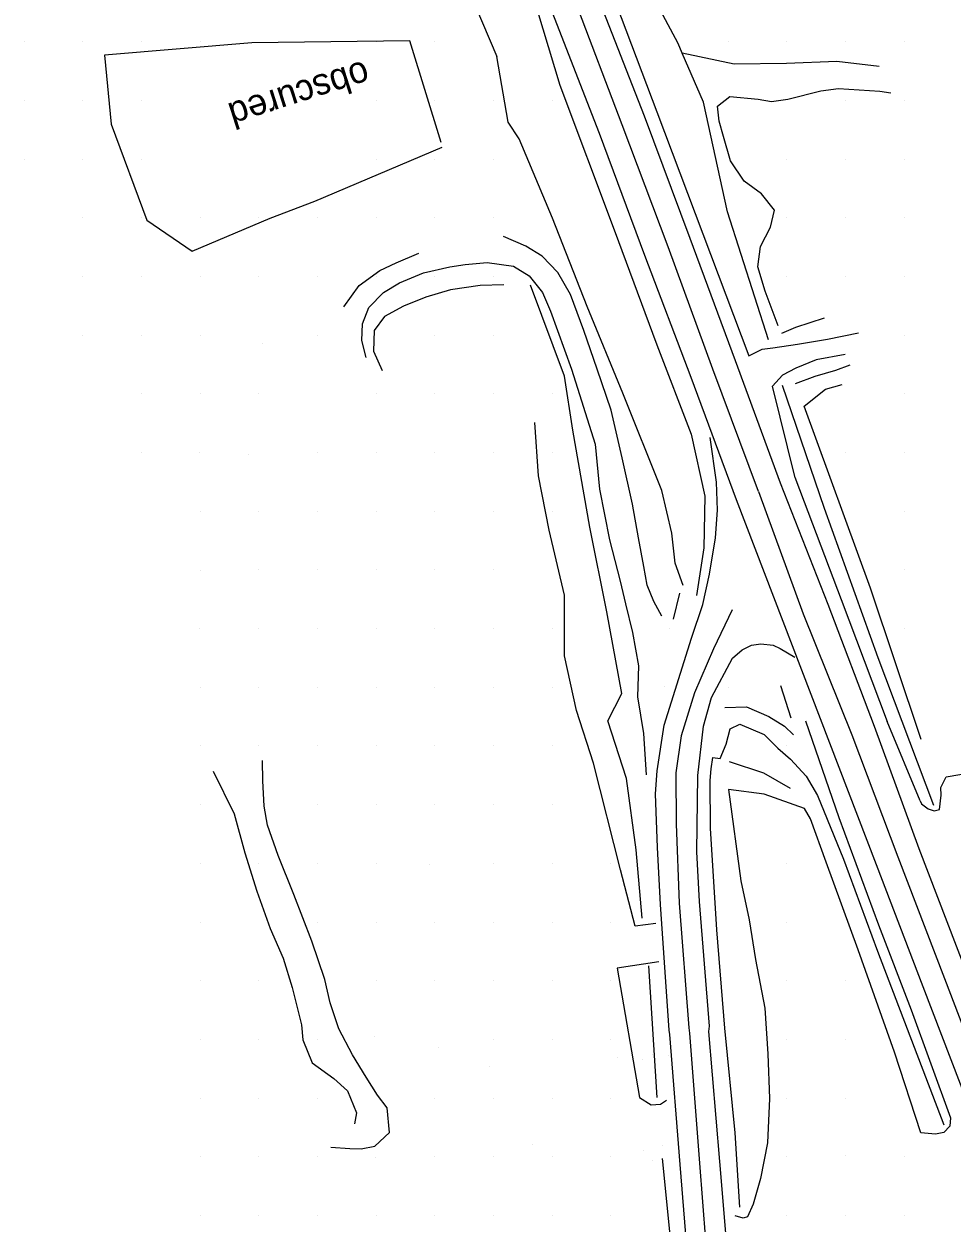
# Model space of a CAD drawing. Extents: x 524772 to 528246, y 273285 to 283088.
# Drawn here: x 527832 to 527974.3, y 273850.8 to 274034.8 of the extents above; entities that cross this region are included whole.
import ezdxf

# ---------------------------------------------------------------- set-up
doc = ezdxf.new("R2010")
doc.units = 0
for name, color, linetype in [('Exist DTM Crownline', 7, 'Continuous'), ('Exist DTM Spot Elevation CELL', 7, 'Continuous'), ('Exist Roads EOP', 7, 'Continuous'), ('Old_Level_12', 7, 'Continuous'), ('PH Exist DTM Breakline', 7, 'Continuous'), ('PH Exist DTM Point', 7, 'Continuous')]:
    doc.layers.add(name, color=color, linetype=linetype)

msp = doc.modelspace()

# ---------------------------------------------------------------- linework, layer by layer
at = {"layer": 'Exist DTM Crownline'}
for points in [[(527923.71, 274019.28), (527916.64, 274037.99), (527909.48, 274056.66), (527902.42, 274075.37), (527895.35, 274094.08), (527888.28, 274112.79), (527881.22, 274131.5)], [(527944.63, 273963.04), (527937.65, 273981.79), (527930.77, 274000.57), (527923.71, 274019.28)], [(527944.63, 273963.04), (527951.5, 273944.26), (527958.94, 273925.69), (527966.01, 273906.98), (527973.17, 273888.31), (527980.33, 273869.63), (527987.3, 273850.89)], [(527940.58, 273944.88), (527937.76, 273938.89), (527934.8, 273932.15), (527932.79, 273925.58), (527931.96, 273919.86), (527932.03, 273912.07), (527932.49, 273899.91)], [(527932.49, 273899.91), (527933.95, 273880.77), (527934.05, 273879.97), (527935.61, 273860.03), (527936.98, 273842.21), (527937.16, 273840.09)]]:
    msp.add_lwpolyline(points, dxfattribs=at)
at = {"layer": 'Exist DTM Spot Elevation CELL'}
for p, q in [((527937.13, 273881.01), (527937.13, 273881.01)), ((527930.96, 273880.43), (527930.96, 273880.43)), ((527933.95, 273880.77), (527933.95, 273880.77)), ((527923.03, 273876.24), (527923.03, 273876.24)), ((527926.81, 273875.86), (527926.81, 273875.86)), ((527928.35, 273876.7), (527928.35, 273876.7)), ((527930.77, 273876.5), (527930.77, 273876.5)), ((527903.36, 273874.89), (527903.36, 273874.89)), ((527929.08, 273870.08), (527929.08, 273870.08)), ((527910, 273862.8), (527910, 273862.8)), ((527929.93, 273862.66), (527929.93, 273862.66)), ((527927.04, 273861.99), (527927.04, 273861.99)), ((527928.39, 273860.4), (527928.39, 273860.4))]:
    msp.add_line(p, q, dxfattribs=at)
at = {"layer": 'Exist Roads EOP'}
for points in [[(527927.17, 274020.59), (527919.92, 274039.22), (527912.85, 274057.93), (527905.78, 274076.65), (527898.72, 274095.36), (527891.65, 274114.07), (527884.68, 274132.81)], [(527920.25, 274017.97), (527912.99, 274036.61), (527906.11, 274055.39), (527898.95, 274074.07), (527891.79, 274092.74), (527884.82, 274111.49), (527877.66, 274130.16)], [(527947.99, 273964.31), (527941.11, 273983.09), (527934.14, 274001.84), (527927.17, 274020.59)], [(527941.26, 273961.77), (527934.29, 273980.52), (527927.22, 273999.23), (527920.25, 274017.97)], [(527934.34, 273940.55), (527936.08, 273945.72), (527937.12, 273950.35), (527938.03, 273955.92), (527938.33, 273960.15), (527938.19, 273964.48), (527937.23, 273971.3)], [(527990.67, 273852.16), (527983.32, 273870.76), (527976.44, 273889.54), (527969.29, 273908.22), (527962.41, 273927), (527955.34, 273945.71), (527947.99, 273964.31)], [(527983.84, 273849.58), (527977.06, 273868.4), (527969.9, 273887.07), (527962.74, 273905.75), (527955.58, 273924.42), (527948.42, 273943.09), (527941.26, 273961.77)], [(527929.6, 273899.68), (527929.13, 273908.45), (527928.86, 273916.64), (527929.08, 273920.2), (527930.16, 273927.18), (527934.34, 273940.55)], [(527940.64, 273937.49), (527942.12, 273938.76), (527943.54, 273939.45), (527945.01, 273939.65), (527946.87, 273939.46), (527947.94, 273938.95), (527950.23, 273937.64)], [(527935.58, 273900.15), (527935.2, 273907.76), (527935.34, 273919.47), (527936.19, 273927.06), (527937.43, 273931.44), (527940.64, 273937.49)], [(527934.27, 273839.87), (527934.05, 273842.12), (527932.61, 273859.8), (527931.06, 273879.74), (527930.96, 273880.43), (527929.6, 273899.68)], [(527940.25, 273840.33), (527940.19, 273842.5), (527938.7, 273860.27), (527937.04, 273880.2), (527937.13, 273881.01), (527935.58, 273900.15)]]:
    msp.add_lwpolyline(points, dxfattribs=at)
at = {"layer": 'Old_Level_12'}
msp.add_lwpolyline([(527895.96, 274016.6), (527891.19, 274032.15), (527866.95, 274031.85), (527844.36, 274029.95), (527845.36, 274019.41), (527850.82, 274004.65), (527857.78, 273999.93), (527869.76, 274004.99), (527876.62, 274007.55), (527896.13, 274015.87)], dxfattribs=at)
at = {"layer": 'PH Exist DTM Breakline'}
for points in [[(527932.33, 274031.74), (527928.09, 274039.74), (527923.18, 274049.35), (527917.81, 274063.13), (527911.32, 274078.89), (527910.46, 274081.35), (527910.25, 274083.11), (527911.02, 274083.95), (527914.25, 274085.41), (527915.51, 274085.41), (527918.1, 274085.78), (527921.83, 274086.1), (527926.27, 274086.59), (527932.39, 274087.35), (527935.26, 274087.76)], [(527907.84, 274077.42), (527914.91, 274058.71), (527921.97, 274040), (527929.04, 274021.29)], [(527846.73, 274042.5), (527852.83, 274043.77), (527859.87, 274045), (527866.06, 274046.14), (527872.74, 274047.39), (527877.8, 274048.29), (527883.23, 274049.22), (527888.44, 274050.26), (527893.6, 274051.24), (527897.81, 274051.99), (527901.67, 274052.04), (527905.21, 274050.83), (527908.96, 274042.71), (527914.19, 274025.36)], [(527892.88, 274046.36), (527898.81, 274043.29), (527904.53, 274029.78)], [(527946.17, 273986.28), (527939.89, 274005.96), (527936.22, 274022.74), (527932.93, 274030.3), (527932.33, 274031.74)], [(527963.12, 274028.25), (527956.63, 274028.98), (527948.92, 274028.68), (527940.91, 274028.6), (527932.93, 274030.3)], [(527907.94, 274017.16), (527906.24, 274019.67), (527904.53, 274029.78)], [(527914.19, 274025.36), (527922.51, 274003.16), (527929.07, 273985.55), (527934.32, 273971.85), (527936.39, 273962.34), (527936.27, 273954.38), (527935.12, 273947.07)], [(527947.65, 273988.45), (527945.67, 273993.75), (527944.54, 273997.5), (527944.92, 274000.64), (527946.49, 274003.61), (527947.07, 274006.22), (527945.09, 274008.71), (527942.42, 274010.62), (527940.35, 274013.74), (527939.26, 274017.51), (527938.61, 274019.87), (527938.33, 274022.17), (527940.25, 274023.62), (527944.61, 274023.22), (527946.63, 274022.88), (527949.15, 274023.2), (527954.18, 274024.52), (527956.92, 274024.88), (527963.25, 274024.47), (527964.92, 274024.2)], [(527929.04, 274021.29), (527936.11, 274002.58), (527943.17, 273983.87)], [(527933.11, 273948.64), (527931.86, 273952.05), (527931.35, 273956.63), (527929.82, 273963.17), (527923.81, 273978.13), (527918.38, 273991.42), (527913.07, 274004.96), (527907.94, 274017.16)], [(527929.8, 273943.89), (527928.58, 273946.15), (527927.55, 273948.65), (527927.04, 273951.53), (527926.22, 273955.95), (527925.31, 273961.09), (527923.71, 273968.2), (527922.02, 273975.49), (527919.89, 273981.78), (527917.86, 273987.76), (527915.82, 273993.25), (527913.89, 273996.61), (527911.48, 273999.14), (527908.95, 274000.67), (527905.52, 274002.18)], [(527881.03, 273991.36), (527883.41, 273994.64), (527886.55, 273996.95), (527889.06, 273998.1), (527892.57, 273999.58)], [(527884.48, 273983.59), (527883.79, 273986.2), (527883.89, 273988.75), (527884.89, 273991.26), (527887.12, 273993.59), (527889.6, 273995.06), (527893.26, 273996.59), (527897.31, 273997.51), (527899.63, 273997.87), (527903.03, 273998.17), (527907.08, 273997.58), (527909.47, 273996.13), (527911.53, 273993.54), (527912.73, 273990.68), (527915.95, 273981.78), (527919.59, 273970.31), (527920.27, 273963.41), (527921.77, 273955.61), (527923.4, 273949.3), (527924.26, 273945.81), (527925.34, 273941.42), (527926.23, 273936.29), (527926.09, 273931.53), (527927.02, 273925.9), (527927.42, 273919.57)], [(527905.58, 273994.74), (527901.96, 273994.63), (527897.39, 273993.98), (527893.64, 273992.86), (527890.18, 273991.49), (527887.3, 273989.87), (527885.71, 273987.76), (527885.61, 273984.58), (527886.93, 273981.59)], [(527926.81, 273897.6), (527925.9, 273908.07), (527924.42, 273918.99), (527921.51, 273927.85), (527923.67, 273932.03), (527921.37, 273944.59), (527918.78, 273957.57), (527916.14, 273972.45), (527914.89, 273980.71), (527909.69, 273994.71)], [(527954.7, 273989.61), (527950.33, 273988.21), (527948.16, 273987.29)], [(527943.17, 273983.87), (527945.21, 273984.85), (527946.86, 273985.07), (527950.64, 273985.62), (527955.21, 273986.4), (527959.95, 273987.4)], [(527957.91, 273984.03), (527953.47, 273983.26), (527950.37, 273981.94), (527948.32, 273980.9), (527946.77, 273979.2)], [(527950.31, 273979.59), (527953.35, 273980.73), (527956.48, 273981.65), (527958.71, 273982.46)], [(527950.24, 273965.16), (527946.77, 273979.2)], [(527971.52, 273914.88), (527963.01, 273937.53), (527954.77, 273960.45), (527948.34, 273979.32)], [(527969.6, 273925), (527961.8, 273948.21), (527951.64, 273976.15), (527954.91, 273978.74), (527957.47, 273979.45)], [(527928.88, 273896.76), (527925.7, 273896.37), (527923.48, 273904.98), (527919.34, 273921.34), (527916.72, 273929.43), (527914.87, 273937.84), (527914.89, 273947.12), (527912.54, 273957.09), (527910.92, 273965.46), (527910.34, 273973.6)], [(527950.24, 273965.16), (527950.36, 273964.85), (527957.3, 273946.45), (527964.37, 273927.74)], [(527931.62, 273943.43), (527932.57, 273947.45)], [(527949.65, 273928.27), (527948.04, 273933.23)], [(527939.46, 273929.91), (527942.8, 273930), (527946.21, 273928.51), (527948.65, 273927.06), (527950.01, 273925.72)], [(527941.78, 273853.25), (527941.04, 273864.64), (527939.45, 273880.72), (527938.26, 273895.81), (527937.29, 273911.41), (527937.23, 273918.73), (527937.36, 273920.5), (527937.61, 273922.24), (527938.77, 273922.07), (527939.66, 273924.29), (527940.27, 273926.62), (527941.8, 273927.33), (527945.49, 273925.78), (527947.62, 273923.69), (527949.52, 273921.98), (527951.96, 273919.35), (527953.68, 273916.4), (527957.69, 273906.63), (527962.87, 273892.51), (527973.07, 273865.91)], [(527951.86, 273927.87), (527956.96, 273913.02), (527963.02, 273896.58), (527968.04, 273883.54), (527974.09, 273866.96), (527973.97, 273865.69), (527973.08, 273864.71), (527971.76, 273864.47), (527969.55, 273864.66), (527965.5, 273877.05), (527959.94, 273892.74), (527955.01, 273906.19), (527952.59, 273912.83), (527951.7, 273914.39), (527945.52, 273916.62), (527940.04, 273917.32), (527941.95, 273903.3), (527943.21, 273897.35), (527944.2, 273891.27), (527945.61, 273883.78), (527946.08, 273876.8), (527946.34, 273869.92), (527946.02, 273863.1), (527944.94, 273857.66), (527943.83, 273853.72), (527942.96, 273851.77), (527942.31, 273851.58), (527941.07, 273851.92)], [(527969.45, 273915.6), (527964.37, 273927.74)], [(527879.07, 273862.46), (527881.98, 273862.24), (527883.7, 273862.18), (527885.82, 273862.59), (527888.06, 273864.71), (527887.67, 273868.47), (527886.21, 273870.46), (527884.48, 273873.18), (527882.37, 273876.62), (527880.26, 273880.62), (527878.96, 273884.62), (527878.13, 273888.19), (527876.12, 273894.04), (527873.38, 273901.23), (527870.99, 273907.21), (527869.32, 273911.85), (527868.81, 273914.79), (527868.61, 273918.64), (527868.6, 273921.76)], [(527949.55, 273917.5), (527945.46, 273919.85), (527940.17, 273921.55)], [(527860.99, 273920.16), (527864.23, 273913.61), (527865.85, 273907.62), (527867.69, 273901.75), (527869.76, 273895.99), (527871.72, 273891.45), (527873.12, 273886.95), (527873.96, 273883.7), (527874.54, 273881.24), (527874.77, 273878.95), (527876.21, 273875.38), (527879.49, 273872.97), (527881.6, 273871.12), (527882.97, 273867.75), (527882.7, 273866.03)], [(527969.45, 273915.6), (527969.61, 273915.15), (527970.65, 273914.36), (527971.58, 273914.04), (527972.41, 273914.24), (527972.66, 273916.46), (527972.6, 273917.64), (527973.44, 273919.25), (527977.28, 273919.94), (527982.78, 273919.75), (527987.06, 273918.77), (527993.52, 273918.54), (528001.23, 273918.35), (528009.16, 273917.46), (528016.36, 273917.09), (528021.37, 273917.14), (528026.15, 273916.47), (528030.9, 273914.94), (528034.69, 273914.22), (528039.18, 273914.54)], [(527929.36, 273890.87), (527922.94, 273889.9), (527926.37, 273870.09), (527928.16, 273868.97), (527929.63, 273869.04), (527930.51, 273869.68)], [(527929.08, 273870.08), (527927.83, 273890.3)], [(527933.38, 273821.87), (527932.07, 273839.29), (527929.9, 273860.71)]]:
    msp.add_lwpolyline(points, dxfattribs=at)
at = {"layer": 'PH Exist DTM Point'}
for p, q in [((527832, 274032), (527832, 274032)), ((527841, 274032), (527841, 274032)), ((527850, 274032), (527850, 274032)), ((527859, 274032), (527859, 274032)), ((527886, 274032), (527886, 274032)), ((527895, 274032), (527895, 274032)), ((527939.98, 274032.01), (527939.98, 274032.01)), ((527949, 274032), (527949, 274032)), ((527958, 274032), (527958, 274032)), ((527966.96, 274032.02), (527966.96, 274032.02)), ((527832, 274023), (527832, 274023)), ((527841, 274023), (527841, 274023)), ((527850, 274023), (527850, 274023)), ((527886, 274023), (527886, 274023)), ((527895, 274023), (527895, 274023)), ((527904, 274023), (527904, 274023)), ((527913, 274023), (527913, 274023)), ((527958, 274023), (527958, 274023)), ((527966.99, 274023.01), (527966.99, 274023.01)), ((527832, 274014), (527832, 274014)), ((527841, 274014), (527841, 274014)), ((527850, 274014), (527850, 274014)), ((527886, 274014), (527886, 274014)), ((527895, 274014), (527895, 274014)), ((527904, 274014), (527904, 274014)), ((527949, 274014), (527949, 274014)), ((527958, 274014), (527958, 274014)), ((527967, 274014), (527967, 274014)), ((527841, 274005), (527841, 274005)), ((527850, 274005), (527850, 274005)), ((527859, 274005), (527859, 274005)), ((527867.99, 274005.03), (527867.99, 274005.03)), ((527877, 274005), (527877, 274005)), ((527886, 274005), (527886, 274005)), ((527895, 274005), (527895, 274005)), ((527904, 274005), (527904, 274005)), ((527949, 274005), (527949, 274005)), ((527958, 274005), (527958, 274005)), ((527967, 274005), (527967, 274005)), ((527841.01, 273995.99), (527841.01, 273995.99)), ((527850, 273996), (527850, 273996)), ((527859, 273996), (527859, 273996)), ((527868.03, 273996.01), (527868.03, 273996.01)), ((527877, 273996), (527877, 273996)), ((527886, 273996), (527886, 273996)), ((527895, 273996), (527895, 273996)), ((527904, 273996), (527904, 273996)), ((527949, 273996), (527949, 273996)), ((527958, 273996), (527958, 273996)), ((527967, 273996), (527967, 273996)), ((527841.01, 273986.93), (527841.01, 273986.93)), ((527850, 273987), (527850, 273987)), ((527859, 273987), (527859, 273987)), ((527868.65, 273985.72), (527868.65, 273985.72)), ((527876.99, 273987.01), (527876.99, 273987.01)), ((527895, 273987), (527895, 273987)), ((527904, 273987), (527904, 273987)), ((527967, 273987), (527967, 273987)), ((527850, 273978), (527850, 273978)), ((527859, 273978), (527859, 273978)), ((527868, 273978), (527868, 273978)), ((527886, 273978), (527886, 273978)), ((527895, 273978), (527895, 273978)), ((527904, 273978), (527904, 273978)), ((527913, 273978), (527913, 273978)), ((527967, 273978), (527967, 273978)), ((527850, 273969), (527850, 273969)), ((527858.98, 273969.02), (527858.98, 273969.02)), ((527866.43, 273968.76), (527866.43, 273968.76)), ((527877.06, 273968.96), (527877.06, 273968.96)), ((527886.01, 273968.99), (527886.01, 273968.99)), ((527895, 273969), (527895, 273969)), ((527903.98, 273969.05), (527903.98, 273969.05)), ((527913, 273969), (527913, 273969)), ((527958, 273969), (527958, 273969)), ((527967, 273969), (527967, 273969)), ((527859.04, 273959.95), (527859.04, 273959.95)), ((527868, 273960), (527868, 273960)), ((527877, 273960), (527877, 273960)), ((527886, 273960), (527886, 273960)), ((527895, 273960), (527895, 273960)), ((527904, 273960), (527904, 273960)), ((527913, 273960), (527913, 273960)), ((527967, 273960), (527967, 273960)), ((527859.02, 273950.98), (527859.02, 273950.98)), ((527868, 273951), (527868, 273951)), ((527877, 273951), (527877, 273951)), ((527886, 273951), (527886, 273951)), ((527895, 273951.01), (527895, 273951.01)), ((527904, 273951), (527904, 273951)), ((527967, 273951), (527967, 273951)), ((527858.96, 273942.02), (527858.96, 273942.02)), ((527868, 273942), (527868, 273942)), ((527877, 273942), (527877, 273942)), ((527886, 273942), (527886, 273942)), ((527895, 273942), (527895, 273942)), ((527904, 273942), (527904, 273942)), ((527913, 273942), (527913, 273942)), ((527931, 273942), (527931, 273942)), ((527967, 273942), (527967, 273942)), ((527859, 273933), (527859, 273933)), ((527868, 273933), (527868, 273933)), ((527877, 273933), (527877, 273933)), ((527886, 273933), (527886, 273933)), ((527895, 273933), (527895, 273933)), ((527904, 273933), (527904, 273933)), ((527913, 273933), (527913, 273933)), ((527930.27, 273933.15), (527930.27, 273933.15)), ((527940.09, 273932.98), (527940.09, 273932.98)), ((527859, 273924), (527859, 273924)), ((527868, 273924), (527868, 273924)), ((527877, 273924), (527877, 273924)), ((527886, 273924), (527886, 273924)), ((527895, 273924), (527895, 273924)), ((527904, 273924), (527904, 273924)), ((527913, 273924), (527913, 273924)), ((527949, 273924), (527949, 273924)), ((527859, 273915), (527859, 273915)), ((527877, 273915), (527877, 273915)), ((527886, 273915), (527886, 273915)), ((527895, 273915), (527895, 273915)), ((527904, 273915), (527904, 273915)), ((527913, 273915), (527913, 273915)), ((527859, 273906), (527859, 273906)), ((527868, 273906), (527868, 273906)), ((527877, 273906), (527877, 273906)), ((527886, 273906), (527886, 273906)), ((527894.15, 273905.89), (527894.15, 273905.89)), ((527904, 273906), (527904, 273906)), ((527913, 273906), (527913, 273906)), ((527922, 273906), (527922, 273906)), ((527949, 273906), (527949, 273906)), ((527859, 273897), (527859, 273897)), ((527877, 273897), (527877, 273897)), ((527886, 273897), (527886, 273897)), ((527895, 273897), (527895, 273897)), ((527904, 273897), (527904, 273897)), ((527913, 273897), (527913, 273897)), ((527922, 273897), (527922, 273897)), ((527949, 273897), (527949, 273897)), ((527859, 273888), (527859, 273888)), ((527868, 273888), (527868, 273888)), ((527886, 273888), (527886, 273888)), ((527895, 273888), (527895, 273888)), ((527904.04, 273887.96), (527904.04, 273887.96)), ((527913, 273888), (527913, 273888)), ((527922, 273888), (527922, 273888)), ((527949, 273888), (527949, 273888)), ((527958, 273888), (527958, 273888)), ((527859, 273879), (527859, 273879)), ((527868, 273879), (527868, 273879)), ((527877, 273879), (527877, 273879)), ((527885.82, 273879.49), (527885.82, 273879.49)), ((527904, 273879), (527904, 273879)), ((527913, 273879), (527913, 273879)), ((527922, 273879), (527922, 273879)), ((527949, 273879), (527949, 273879)), ((527958, 273879), (527958, 273879)), ((527895.59, 273877.78), (527895.59, 273877.78)), ((527859, 273870), (527859, 273870)), ((527868, 273870), (527868, 273870)), ((527877, 273870), (527877, 273870)), ((527895, 273870), (527895, 273870)), ((527904, 273870), (527904, 273870)), ((527913, 273870), (527913, 273870)), ((527922, 273870), (527922, 273870)), ((527949, 273870), (527949, 273870)), ((527958, 273870), (527958, 273870)), ((527859, 273861), (527859, 273861)), ((527868, 273861), (527868, 273861)), ((527877, 273861), (527877, 273861)), ((527885.86, 273860.95), (527885.86, 273860.95)), ((527895, 273861), (527895, 273861)), ((527904, 273861), (527904, 273861)), ((527913, 273861), (527913, 273861)), ((527922, 273861), (527922, 273861)), ((527949, 273861), (527949, 273861)), ((527957.94, 273861.15), (527957.94, 273861.15)), ((527967, 273861), (527967, 273861)), ((527859, 273852), (527859, 273852)), ((527868, 273852), (527868, 273852)), ((527877, 273852), (527877, 273852)), ((527886, 273852), (527886, 273852)), ((527895, 273852), (527895, 273852)), ((527904, 273852), (527904, 273852)), ((527913, 273852), (527913, 273852)), ((527922, 273852), (527922, 273852)), ((527949, 273852), (527949, 273852)), ((527958, 273852), (527958, 273852)), ((527967, 273852), (527967, 273852))]:
    msp.add_line(p, q, dxfattribs=at)

# ---------------------------------------------------------------- texts
at = {"layer": 'Old_Level_12'}
msp.add_text('obscured', height=4.05, rotation=197.6643, dxfattribs=at).set_placement((527884.23, 274029.21))

doc.saveas('drawing.dxf')
